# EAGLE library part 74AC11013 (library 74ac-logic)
Dual 4-input NAND, schmitt trigger
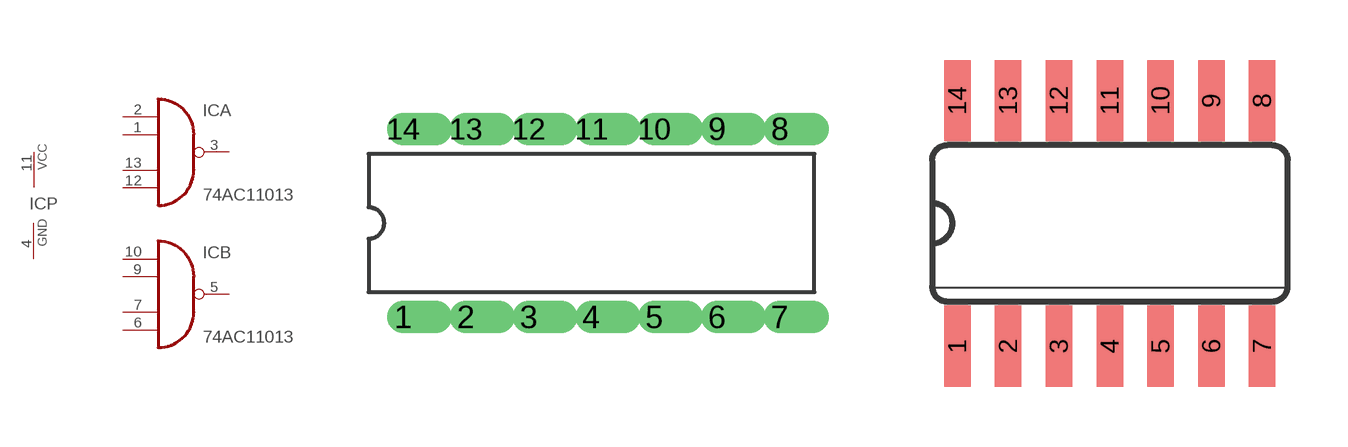
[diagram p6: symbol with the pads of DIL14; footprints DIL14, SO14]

Designator prefix IC; gates A=7411013 B=7411013 P=PWRN

## 74AC11013  [DIL14]
1  A:I1  in
2  A:I0  in
3  A:O  out
4  P:GND  pwr
5  B:O  out
6  B:I3  in
7  B:I2  in
9  B:I1  in
10  B:I0  in
11  P:VCC  pwr
12  A:I3  in
13  A:I2  in

## 74AC11013D  [SO14]
Pads as for DIL14

## Footprint DIL14 (pad centres in mm)
Dual In Line
drill 0.813 offset: 1 -7.62,-3.81; 2 -5.08,-3.81; 3 -2.54,-3.81; 4 0,-3.81; 5 2.54,-3.81; 6 5.08,-3.81; 7 7.62,-3.81; 8 7.62,3.81; 9 5.08,3.81; 10 2.54,3.81; 11 0,3.81; 12 -2.54,3.81; 13 -5.08,3.81; 14 -7.62,3.81

## Footprint SO14 (pad centres in mm)
Small Outline package 150 mil
smd 0.66 x 2.032: 1 -3.81,-3.073; 2 -2.54,-3.073; 3 -1.27,-3.073; 4 0,-3.073; 5 1.27,-3.073; 6 2.54,-3.073; 7 3.81,-3.073; 8 3.81,3.073; 9 2.54,3.073; 10 1.27,3.073; 11 0,3.073; 12 -1.27,3.073; 13 -2.54,3.073; 14 -3.81,3.073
